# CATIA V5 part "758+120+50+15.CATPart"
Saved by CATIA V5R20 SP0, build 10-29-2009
Part number: 758+120+50+15
Revision: TUTTO
Definition: NON CONOSCIUTO
Nomenclature: 758+120+50+15
Source: Unknown
Bounding box of the stored display mesh (mm): x -60 to 60, y 0 to 50, z -60 to 60
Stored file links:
  C:\Users\Utente\Desktop\IO LAVORO\3D X SITO CF\X 3D SITO CF 27-09-2020\758\758+120+50+15.CATPart
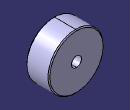
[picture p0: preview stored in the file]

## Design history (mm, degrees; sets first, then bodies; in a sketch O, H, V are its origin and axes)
Body1 "Smusso 2x45°" (main body)
  Solid1: solid without history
